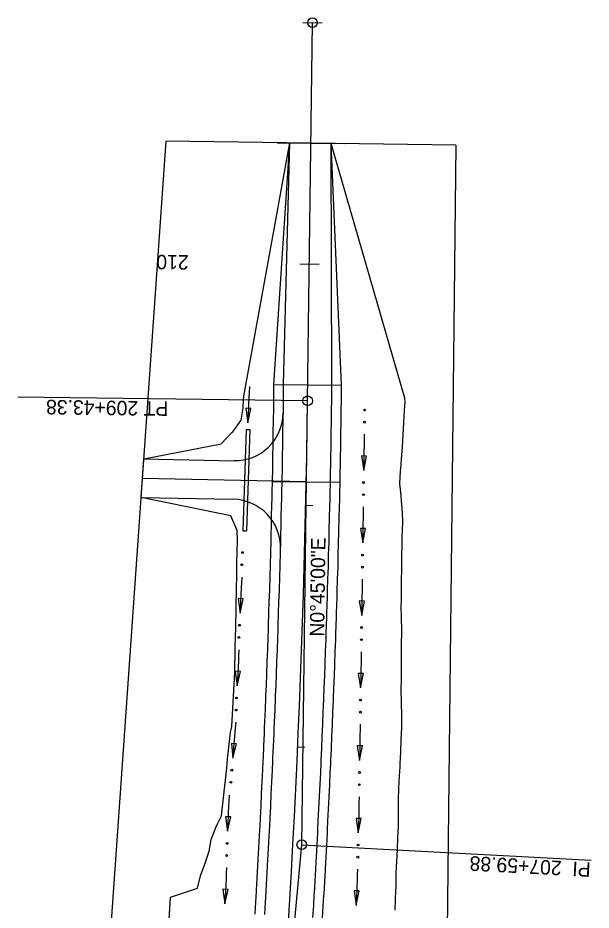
# Model space of a CAD drawing. Extents: x 1 to 1477871, y 1 to 1872901.
# Drawn here: x 1438530.6 to 1438768, y 1870667.7 to 1871037 of the extents above; entities that cross this region are included whole.
import ezdxf

# ---------------------------------------------------------------- set-up
doc = ezdxf.new("R2010")
doc.units = 0
for name, color, linetype in [('R_Drive', 7, 'Continuous'), ('R_Horz Alg', 7, 'Continuous'), ('R_Horz Alg Annot', 7, 'Continuous'), ('R_No Plot', 7, 'Continuous'), ('R_Proposed Const Limits_Cut', 7, 'Continuous'), ('R_Proposed Road_Lane', 7, 'Continuous'), ('R_Proposed Road_Shoulder', 7, 'Continuous'), ('R_ROW', 7, 'Continuous'), ('R_Water', 7, 'Continuous')]:
    doc.layers.add(name, color=color, linetype=linetype)

msp = doc.modelspace()

# ---------------------------------------------------------------- linework, layer by layer
at = {"layer": 'R_Drive'}
for p, q in [((1438581.64, 1870838.51), (1438582.76, 1870854.5)), ((1438582.76, 1870854.5), (1438620.12, 1870853.73)), ((1438581.64, 1870838.51), (1438619.8, 1870837.74))]:
    msp.add_line(p, q, dxfattribs=at)
for centre, start, end in [((1438620.53, 1870873.73), 268.8328, 359.0508), ((1438619.39, 1870817.74), 358.6104, 88.8328)]:
    msp.add_arc(centre, 20, start, end, dxfattribs=at)
at = {"layer": 'R_Horz Alg'}
msp.add_line((1438650.59, 1870878.5), (1438652.63, 1871034.97), dxfattribs=at)
msp.add_arc((1434067.32, 1870938.5), 4583.66, 354.66013, 359.25, dxfattribs=at)
at = {"layer": 'R_Horz Alg Annot'}
for p, q in [((1438648.18, 1870694.82), (1438650.59, 1870878.5)), ((1438631.09, 1870511.92), (1438648.18, 1870694.82))]:
    msp.add_line(p, q, dxfattribs=at)
for points in [[(1438648.63, 1871035.02), (1438656.63, 1871034.92)], [(1438647.33, 1870935.17), (1438655.33, 1870935.06)], [(1438650.59, 1870878.5), (1438530.6, 1870880.07)], [(1438652.81, 1870835.06), (1438649.81, 1870835.13)], [(1438649.46, 1870735.05), (1438646.47, 1870735.18)], [(1438648.18, 1870694.82), (1438768.01, 1870688.45)]]:
    msp.add_lwpolyline(points, dxfattribs=at)
for centre in [(1438652.63, 1871034.97), (1438650.59, 1870878.5), (1438648.18, 1870694.82)]:
    msp.add_circle(centre, 2, dxfattribs=at)
at = {"layer": 'R_No Plot'}
for p, q in [((1438637.98, 1870985.29), (1438665.98, 1870984.93)), ((1438636.67, 1870885.3), (1438664.67, 1870884.93)), ((1438582.22, 1870846.5), (1438650.03, 1870845.12)), ((1438636.15, 1870845.17), (1438664.15, 1870844.8))]:
    msp.add_line(p, q, dxfattribs=at)
at = {"layer": 'R_Proposed Const Limits_Cut'}
for points in [[(1438620.41, 1870766.19), (1438620.52, 1870770.74), (1438620.53, 1870771.16), (1438620.64, 1870776.13), (1438620.76, 1870781.1), (1438620.83, 1870784.26), (1438620.86, 1870786.07), (1438620.97, 1870791.04), (1438621.07, 1870796.01), (1438621.1, 1870797.78), (1438621.17, 1870800.98), (1438621.26, 1870805.94), (1438621.35, 1870810.91), (1438621.35, 1870811.29), (1438621.43, 1870815.88), (1438621.51, 1870820.85), (1438621.41, 1870824.81), (1438621.01, 1870825.83), (1438618.77, 1870830.86), (1438581.64, 1870838.51), (1438582.76, 1870854.5), (1438614.74, 1870860.73), (1438619.28, 1870865.4), (1438619.56, 1870865.61), (1438623.12, 1870870.53), (1438623.97, 1870875.49), (1438624.08, 1870878.84), (1438624.16, 1870880.46), (1438643.21, 1870985.22)], [(1438686.87, 1870667.71), (1438687.02, 1870672.13), (1438687.04, 1870672.75), (1438687.21, 1870677.8), (1438687.31, 1870682.85), (1438687.42, 1870685.86), (1438687.51, 1870687.89), (1438687.75, 1870692.93), (1438687.97, 1870697.98), (1438688.04, 1870699.57), (1438688.2, 1870703.02), (1438688.23, 1870708.07), (1438688.19, 1870713.12), (1438688.2, 1870713.31), (1438688.43, 1870718.17), (1438688.68, 1870723.21), (1438688.86, 1870727.02), (1438688.92, 1870728.25), (1438689.25, 1870733.28), (1438689.4, 1870738.33), (1438689.48, 1870740.73), (1438689.56, 1870743.37), (1438689.65, 1870748.42), (1438689.52, 1870753.48), (1438689.49, 1870754.47), (1438689.38, 1870758.53), (1438689.48, 1870763.58), (1438689.49, 1870768.2), (1438689.49, 1870768.62), (1438689.5, 1870773.67), (1438689.52, 1870778.72), (1438689.59, 1870781.93), (1438689.56, 1870783.77), (1438689.47, 1870788.82), (1438689.4, 1870793.87), (1438689.45, 1870795.66), (1438689.46, 1870798.91), (1438689.51, 1870803.96), (1438689.56, 1870809), (1438689.57, 1870809.39), (1438689.62, 1870814.05), (1438689.72, 1870819.09), (1438689.81, 1870823.1), (1438689.84, 1870824.13), (1438689.96, 1870829.17), (1438689.78, 1870834.22), (1438689.54, 1870836.83), (1438689.31, 1870839.28), (1438688.84, 1870844.33), (1438689.05, 1870849.37), (1438689.15, 1870850.56), (1438689.46, 1870854.41), (1438689.87, 1870859.44), (1438690.16, 1870864.26), (1438690.17, 1870864.48), (1438690.46, 1870869.52), (1438690.75, 1870874.56), (1438690.94, 1870877.97), (1438690.9, 1870879.59), (1438660.36, 1870985)], [(1438593.27, 1870664.06), (1438593.51, 1870668.22), (1438593.88, 1870673.16), (1438604.97, 1870676.86), (1438605.1, 1870677.47), (1438606.39, 1870682.36), (1438608.11, 1870687.23), (1438609.12, 1870690.14), (1438609.8, 1870692.11), (1438610.69, 1870697.03), (1438612.54, 1870701.9), (1438613.32, 1870703.44), (1438614.87, 1870706.76), (1438615.44, 1870711.7), (1438616.01, 1870716.65), (1438616.03, 1870716.83), (1438616.56, 1870721.59), (1438617.11, 1870726.54), (1438617.36, 1870730.29), (1438617.5, 1870731.5), (1438618.06, 1870736.44), (1438618.72, 1870741.39), (1438619.27, 1870743.74), (1438620.41, 1870766.19)]]:
    msp.add_lwpolyline(points, dxfattribs=at)
at = {"layer": 'R_Proposed Road_Lane'}
for p, q in [((1438640.67, 1870885.25), (1438643.21, 1870985.22)), ((1438643.21, 1870985.22), (1438660.36, 1870985)), ((1438660.67, 1870884.99), (1438660.36, 1870985))]:
    msp.add_line(p, q, dxfattribs=at)
for points in [[(1438632.85, 1870665.87), (1438633.14, 1870670.85), (1438633.4, 1870675.22), (1438633.43, 1870675.84), (1438633.71, 1870680.82), (1438633.99, 1870685.8), (1438634.16, 1870688.77), (1438634.27, 1870690.78), (1438634.53, 1870695.76), (1438634.79, 1870700.74), (1438634.88, 1870702.32), (1438635.05, 1870705.73), (1438635.3, 1870710.71), (1438635.55, 1870715.69), (1438635.56, 1870715.88), (1438635.79, 1870720.68), (1438636.02, 1870725.66), (1438636.2, 1870729.43), (1438636.25, 1870730.64), (1438636.48, 1870735.63), (1438636.7, 1870740.61), (1438636.8, 1870742.99), (1438636.91, 1870745.59), (1438637.12, 1870750.58), (1438637.32, 1870755.56), (1438637.36, 1870756.54), (1438637.52, 1870760.55), (1438637.71, 1870765.54), (1438637.88, 1870770.1), (1438637.89, 1870770.52), (1438638.07, 1870775.51), (1438638.25, 1870780.49), (1438638.36, 1870783.67), (1438638.42, 1870785.48), (1438638.58, 1870790.47), (1438638.74, 1870795.45), (1438638.8, 1870797.23), (1438638.89, 1870800.44), (1438639.04, 1870805.43), (1438639.18, 1870810.41), (1438639.2, 1870810.79), (1438639.32, 1870815.4), (1438639.45, 1870820.39), (1438639.55, 1870824.36), (1438639.58, 1870825.38), (1438639.7, 1870830.36), (1438639.81, 1870835.35), (1438639.87, 1870837.93), (1438639.93, 1870840.34), (1438640.03, 1870845.33), (1438640.13, 1870850.31), (1438640.15, 1870851.49), (1438640.22, 1870855.3), (1438640.31, 1870860.29), (1438640.39, 1870865.06), (1438640.39, 1870865.28), (1438640.47, 1870870.27), (1438640.54, 1870875.26), (1438640.59, 1870878.63), (1438640.61, 1870880.25), (1438640.67, 1870885.25)], [(1438652.81, 1870664.68), (1438653.11, 1870669.69), (1438653.36, 1870674.07), (1438653.4, 1870674.69), (1438653.68, 1870679.69), (1438653.96, 1870684.69), (1438654.13, 1870687.68), (1438654.24, 1870689.7), (1438654.5, 1870694.7), (1438654.77, 1870699.7), (1438654.85, 1870701.29), (1438655.03, 1870704.71), (1438655.28, 1870709.71), (1438655.52, 1870714.72), (1438655.53, 1870714.9), (1438655.77, 1870719.72), (1438656, 1870724.73), (1438656.18, 1870728.52), (1438656.23, 1870729.73), (1438656.46, 1870734.74), (1438656.68, 1870739.75), (1438656.78, 1870742.13), (1438656.89, 1870744.75), (1438657.1, 1870749.76), (1438657.3, 1870754.77), (1438657.34, 1870755.75), (1438657.5, 1870759.77), (1438657.69, 1870764.78), (1438657.86, 1870769.37), (1438657.88, 1870769.79), (1438658.06, 1870774.79), (1438658.24, 1870779.8), (1438658.34, 1870782.99), (1438658.41, 1870784.81), (1438658.57, 1870789.82), (1438658.73, 1870794.83), (1438658.79, 1870796.61), (1438658.89, 1870799.84), (1438659.03, 1870804.84), (1438659.18, 1870809.85), (1438659.19, 1870810.24), (1438659.31, 1870814.86), (1438659.45, 1870819.87), (1438659.55, 1870823.86), (1438659.57, 1870824.88), (1438659.69, 1870829.89), (1438659.81, 1870834.9), (1438659.87, 1870837.49), (1438659.92, 1870839.91), (1438660.03, 1870844.92), (1438660.12, 1870849.93), (1438660.15, 1870851.11), (1438660.22, 1870854.94), (1438660.31, 1870859.95), (1438660.39, 1870864.74), (1438660.39, 1870864.96), (1438660.47, 1870869.97), (1438660.54, 1870874.98), (1438660.58, 1870878.37), (1438660.61, 1870879.99), (1438660.67, 1870884.99)]]:
    msp.add_lwpolyline(points, dxfattribs=at)
at = {"layer": 'R_Proposed Road_Shoulder'}
for p, q in [((1438636.67, 1870885.3), (1438643.21, 1870985.22)), ((1438664.67, 1870884.93), (1438660.36, 1870985))]:
    msp.add_line(p, q, dxfattribs=at)
for points in [[(1438628.85, 1870666.11), (1438629.15, 1870671.09), (1438629.4, 1870675.45), (1438629.44, 1870676.06), (1438629.72, 1870681.04), (1438630, 1870686.02), (1438630.16, 1870688.99), (1438630.27, 1870691), (1438630.54, 1870695.97), (1438630.8, 1870700.95), (1438630.88, 1870702.53), (1438631.06, 1870705.93), (1438631.31, 1870710.91), (1438631.55, 1870715.89), (1438631.56, 1870716.07), (1438631.79, 1870720.87), (1438632.03, 1870725.84), (1438632.2, 1870729.61), (1438632.26, 1870730.82), (1438632.48, 1870735.8), (1438632.7, 1870740.78), (1438632.8, 1870743.16), (1438632.91, 1870745.76), (1438633.12, 1870750.75), (1438633.32, 1870755.73), (1438633.36, 1870756.7), (1438633.52, 1870760.71), (1438633.71, 1870765.69), (1438633.88, 1870770.25), (1438633.9, 1870770.67), (1438634.08, 1870775.65), (1438634.25, 1870780.63), (1438634.36, 1870783.8), (1438634.42, 1870785.61), (1438634.58, 1870790.59), (1438634.74, 1870795.58), (1438634.8, 1870797.35), (1438634.9, 1870800.56), (1438635.04, 1870805.54), (1438635.19, 1870810.53), (1438635.2, 1870810.91), (1438635.32, 1870815.51), (1438635.45, 1870820.49), (1438635.55, 1870824.46), (1438635.58, 1870825.47), (1438635.7, 1870830.46), (1438635.82, 1870835.44), (1438635.87, 1870838.01), (1438635.93, 1870840.42), (1438636.03, 1870845.41), (1438636.13, 1870850.39), (1438636.15, 1870851.57), (1438636.22, 1870855.38), (1438636.31, 1870860.36), (1438636.39, 1870865.12), (1438636.39, 1870865.34), (1438636.47, 1870870.33), (1438636.54, 1870875.31), (1438636.59, 1870878.68), (1438636.61, 1870880.3), (1438636.67, 1870885.3)], [(1438656.8, 1870664.44), (1438657.1, 1870669.45), (1438657.35, 1870673.84), (1438657.39, 1870674.46), (1438657.68, 1870679.46), (1438657.96, 1870684.47), (1438658.12, 1870687.46), (1438658.23, 1870689.48), (1438658.5, 1870694.49), (1438658.76, 1870699.5), (1438658.84, 1870701.08), (1438659.02, 1870704.51), (1438659.27, 1870709.51), (1438659.52, 1870714.52), (1438659.53, 1870714.71), (1438659.76, 1870719.53), (1438660, 1870724.54), (1438660.17, 1870728.33), (1438660.23, 1870729.55), (1438660.45, 1870734.56), (1438660.67, 1870739.57), (1438660.78, 1870741.96), (1438660.89, 1870744.58), (1438661.1, 1870749.59), (1438661.3, 1870754.6), (1438661.34, 1870755.59), (1438661.5, 1870759.62), (1438661.69, 1870764.63), (1438661.86, 1870769.22), (1438661.88, 1870769.64), (1438662.06, 1870774.65), (1438662.23, 1870779.66), (1438662.34, 1870782.85), (1438662.4, 1870784.68), (1438662.57, 1870789.69), (1438662.73, 1870794.7), (1438662.78, 1870796.49), (1438662.88, 1870799.72), (1438663.03, 1870804.73), (1438663.18, 1870809.74), (1438663.19, 1870810.12), (1438663.31, 1870814.75), (1438663.45, 1870819.77), (1438663.55, 1870823.76), (1438663.57, 1870824.78), (1438663.69, 1870829.79), (1438663.81, 1870834.81), (1438663.87, 1870837.4), (1438663.92, 1870839.82), (1438664.02, 1870844.84), (1438664.12, 1870849.85), (1438664.15, 1870851.04), (1438664.22, 1870854.87), (1438664.31, 1870859.88), (1438664.39, 1870864.67), (1438664.39, 1870864.9), (1438664.47, 1870869.91), (1438664.54, 1870874.93), (1438664.58, 1870878.31), (1438664.61, 1870879.94), (1438664.67, 1870884.93)]]:
    msp.add_lwpolyline(points, dxfattribs=at)
at = {"layer": 'R_ROW'}
for p, q in [((1438531.34, 1870121.98), (1438591.99, 1870985.89)), ((1438711.98, 1870984.32), (1438591.99, 1870985.89)), ((1438711.98, 1870984.32), (1438701.19, 1870006.35))]:
    msp.add_line(p, q, dxfattribs=at)
at = {"layer": 'R_Water'}
for p, q in [((1438627.14, 1870875.33), (1438625.03, 1870875.43)), ((1438625.03, 1870875.43), (1438625.79, 1870869.38)), ((1438625.79, 1870869.38), (1438627.14, 1870875.33)), ((1438625.14, 1870866.65), (1438623.73, 1870824.68)), ((1438625.14, 1870866.65), (1438626.64, 1870866.6)), ((1438626.64, 1870866.6), (1438625.23, 1870824.63)), ((1438674.97, 1870855.66), (1438672.86, 1870855.69)), ((1438672.86, 1870855.69), (1438673.83, 1870849.67)), ((1438673.83, 1870849.67), (1438674.97, 1870855.66)), ((1438623.73, 1870824.68), (1438625.23, 1870824.63)), ((1438674.55, 1870825.66), (1438672.43, 1870825.69)), ((1438672.43, 1870825.69), (1438673.41, 1870819.68)), ((1438673.41, 1870819.68), (1438674.55, 1870825.66)), ((1438623.96, 1870796.55), (1438621.85, 1870796.65)), ((1438621.85, 1870796.65), (1438622.61, 1870790.61)), ((1438622.61, 1870790.61), (1438623.96, 1870796.55)), ((1438674.12, 1870795.66), (1438672.01, 1870795.69)), ((1438672.01, 1870795.69), (1438672.98, 1870789.68)), ((1438672.98, 1870789.68), (1438674.12, 1870795.66)), ((1438622.77, 1870766.47), (1438620.65, 1870766.58)), ((1438620.65, 1870766.58), (1438621.41, 1870760.53)), ((1438621.41, 1870760.53), (1438622.77, 1870766.47)), ((1438673.7, 1870765.67), (1438671.58, 1870765.7)), ((1438671.58, 1870765.7), (1438672.56, 1870759.68)), ((1438672.56, 1870759.68), (1438673.7, 1870765.67)), ((1438621.17, 1870736.53), (1438619.06, 1870736.71)), ((1438619.06, 1870736.71), (1438619.6, 1870730.64)), ((1438619.6, 1870730.64), (1438621.17, 1870736.53)), ((1438673.28, 1870735.67), (1438671.16, 1870735.7)), ((1438671.16, 1870735.7), (1438672.13, 1870729.69)), ((1438672.13, 1870729.69), (1438673.28, 1870735.67)), ((1438618.74, 1870706.33), (1438616.63, 1870706.41)), ((1438616.63, 1870706.41), (1438617.45, 1870700.37)), ((1438617.45, 1870700.37), (1438618.74, 1870706.33)), ((1438672.77, 1870705.67), (1438670.65, 1870705.71)), ((1438670.65, 1870705.71), (1438671.57, 1870699.69)), ((1438671.57, 1870699.69), (1438672.77, 1870705.67)), ((1438617.67, 1870676.34), (1438615.55, 1870676.44)), ((1438615.55, 1870676.44), (1438616.31, 1870670.4)), ((1438616.31, 1870670.4), (1438617.67, 1870676.34)), ((1438671.98, 1870675.67), (1438669.87, 1870675.73)), ((1438669.87, 1870675.73), (1438670.73, 1870669.7)), ((1438670.73, 1870669.7), (1438671.98, 1870675.67))]:
    msp.add_line(p, q, dxfattribs=at)
for points in [[(1438626.52, 1870884.37), (1438626.4, 1870881.85), (1438626.31, 1870879.97), (1438626.16, 1870876.87), (1438625.91, 1870871.9), (1438625.79, 1870869.38)], [(1438674.04, 1870864.67), (1438674.01, 1870862.15), (1438673.98, 1870860.27), (1438673.94, 1870857.17), (1438673.87, 1870852.19), (1438673.83, 1870849.67)], [(1438673.61, 1870834.68), (1438673.58, 1870832.16), (1438673.56, 1870830.27), (1438673.51, 1870827.17), (1438673.44, 1870822.19), (1438673.41, 1870819.68)], [(1438623.34, 1870805.59), (1438623.22, 1870803.08), (1438623.13, 1870801.2), (1438622.98, 1870798.1), (1438622.73, 1870793.12), (1438622.61, 1870790.61)], [(1438673.19, 1870804.68), (1438673.16, 1870802.16), (1438673.13, 1870800.28), (1438673.09, 1870797.18), (1438673.02, 1870792.19), (1438672.98, 1870789.68)], [(1438622.15, 1870775.52), (1438622.03, 1870773), (1438621.93, 1870771.12), (1438621.78, 1870768.02), (1438621.54, 1870763.05), (1438621.41, 1870760.53)], [(1438672.76, 1870774.68), (1438672.73, 1870772.16), (1438672.71, 1870770.28), (1438672.66, 1870767.18), (1438672.59, 1870762.2), (1438672.56, 1870759.68)], [(1438620.87, 1870745.59), (1438620.66, 1870743.08), (1438620.5, 1870741.2), (1438620.24, 1870738.11), (1438619.82, 1870733.15), (1438619.6, 1870730.64)], [(1438672.34, 1870744.68), (1438672.31, 1870742.17), (1438672.28, 1870740.28), (1438672.24, 1870737.18), (1438672.17, 1870732.2), (1438672.13, 1870729.69)], [(1438618.04, 1870715.36), (1438617.94, 1870712.85), (1438617.87, 1870710.96), (1438617.75, 1870707.87), (1438617.55, 1870702.89), (1438617.45, 1870700.37)], [(1438671.92, 1870714.69), (1438671.86, 1870712.17), (1438671.82, 1870710.29), (1438671.74, 1870707.19), (1438671.63, 1870702.21), (1438671.57, 1870699.69)], [(1438617.05, 1870685.38), (1438616.93, 1870682.86), (1438616.83, 1870680.98), (1438616.68, 1870677.89), (1438616.44, 1870672.91), (1438616.31, 1870670.4)], [(1438671.22, 1870684.7), (1438671.14, 1870682.18), (1438671.08, 1870680.3), (1438670.98, 1870677.2), (1438670.81, 1870672.22), (1438670.73, 1870669.7)]]:
    msp.add_lwpolyline(points, dxfattribs=at)
for centre in [(1438674.22, 1870874.67), (1438674.14, 1870869.66), (1438673.79, 1870844.67), (1438673.72, 1870839.66), (1438623.59, 1870815.69), (1438673.37, 1870814.67), (1438623.34, 1870810.68), (1438673.29, 1870809.66), (1438622.4, 1870785.61), (1438672.94, 1870784.67), (1438622.14, 1870780.6), (1438672.87, 1870779.66), (1438621.2, 1870755.53), (1438672.52, 1870754.68), (1438620.95, 1870750.53), (1438672.44, 1870749.67), (1438619.21, 1870725.65), (1438672.1, 1870724.68), (1438618.78, 1870720.66), (1438672.02, 1870719.67), (1438617.28, 1870695.37), (1438671.48, 1870694.69), (1438617.07, 1870690.36), (1438671.36, 1870689.68)]:
    msp.add_circle(centre, 0.375, dxfattribs=at)

# ---------------------------------------------------------------- texts
at = {"layer": 'R_Horz Alg Annot'}
for s, rotation, p in [('210', 179.25, (1438601.37, 1870938.77)), ('PT 209+43.38', 179.25, (1438592.94, 1870878.25)), ('N0%%d45\'00"E', 89.25, (1438657.49, 1870780.88)), ('PI  207+59.88', 176.9551, (1438767.96, 1870687.45))]:
    msp.add_text(s, height=6, rotation=rotation, dxfattribs=at).set_placement(p)

doc.saveas('drawing.dxf')
